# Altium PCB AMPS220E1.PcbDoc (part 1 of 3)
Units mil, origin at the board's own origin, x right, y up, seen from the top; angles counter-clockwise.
Board outline 4800 x 2800 mil, 4 copper layers (Top Layer, GND_Split, GROUND, Bottom Layer), stack 62.6 mil thick; 263 components, 127 nets, 663 pads, 225 vias.
Unrouted connection lines stored in the file: 38.
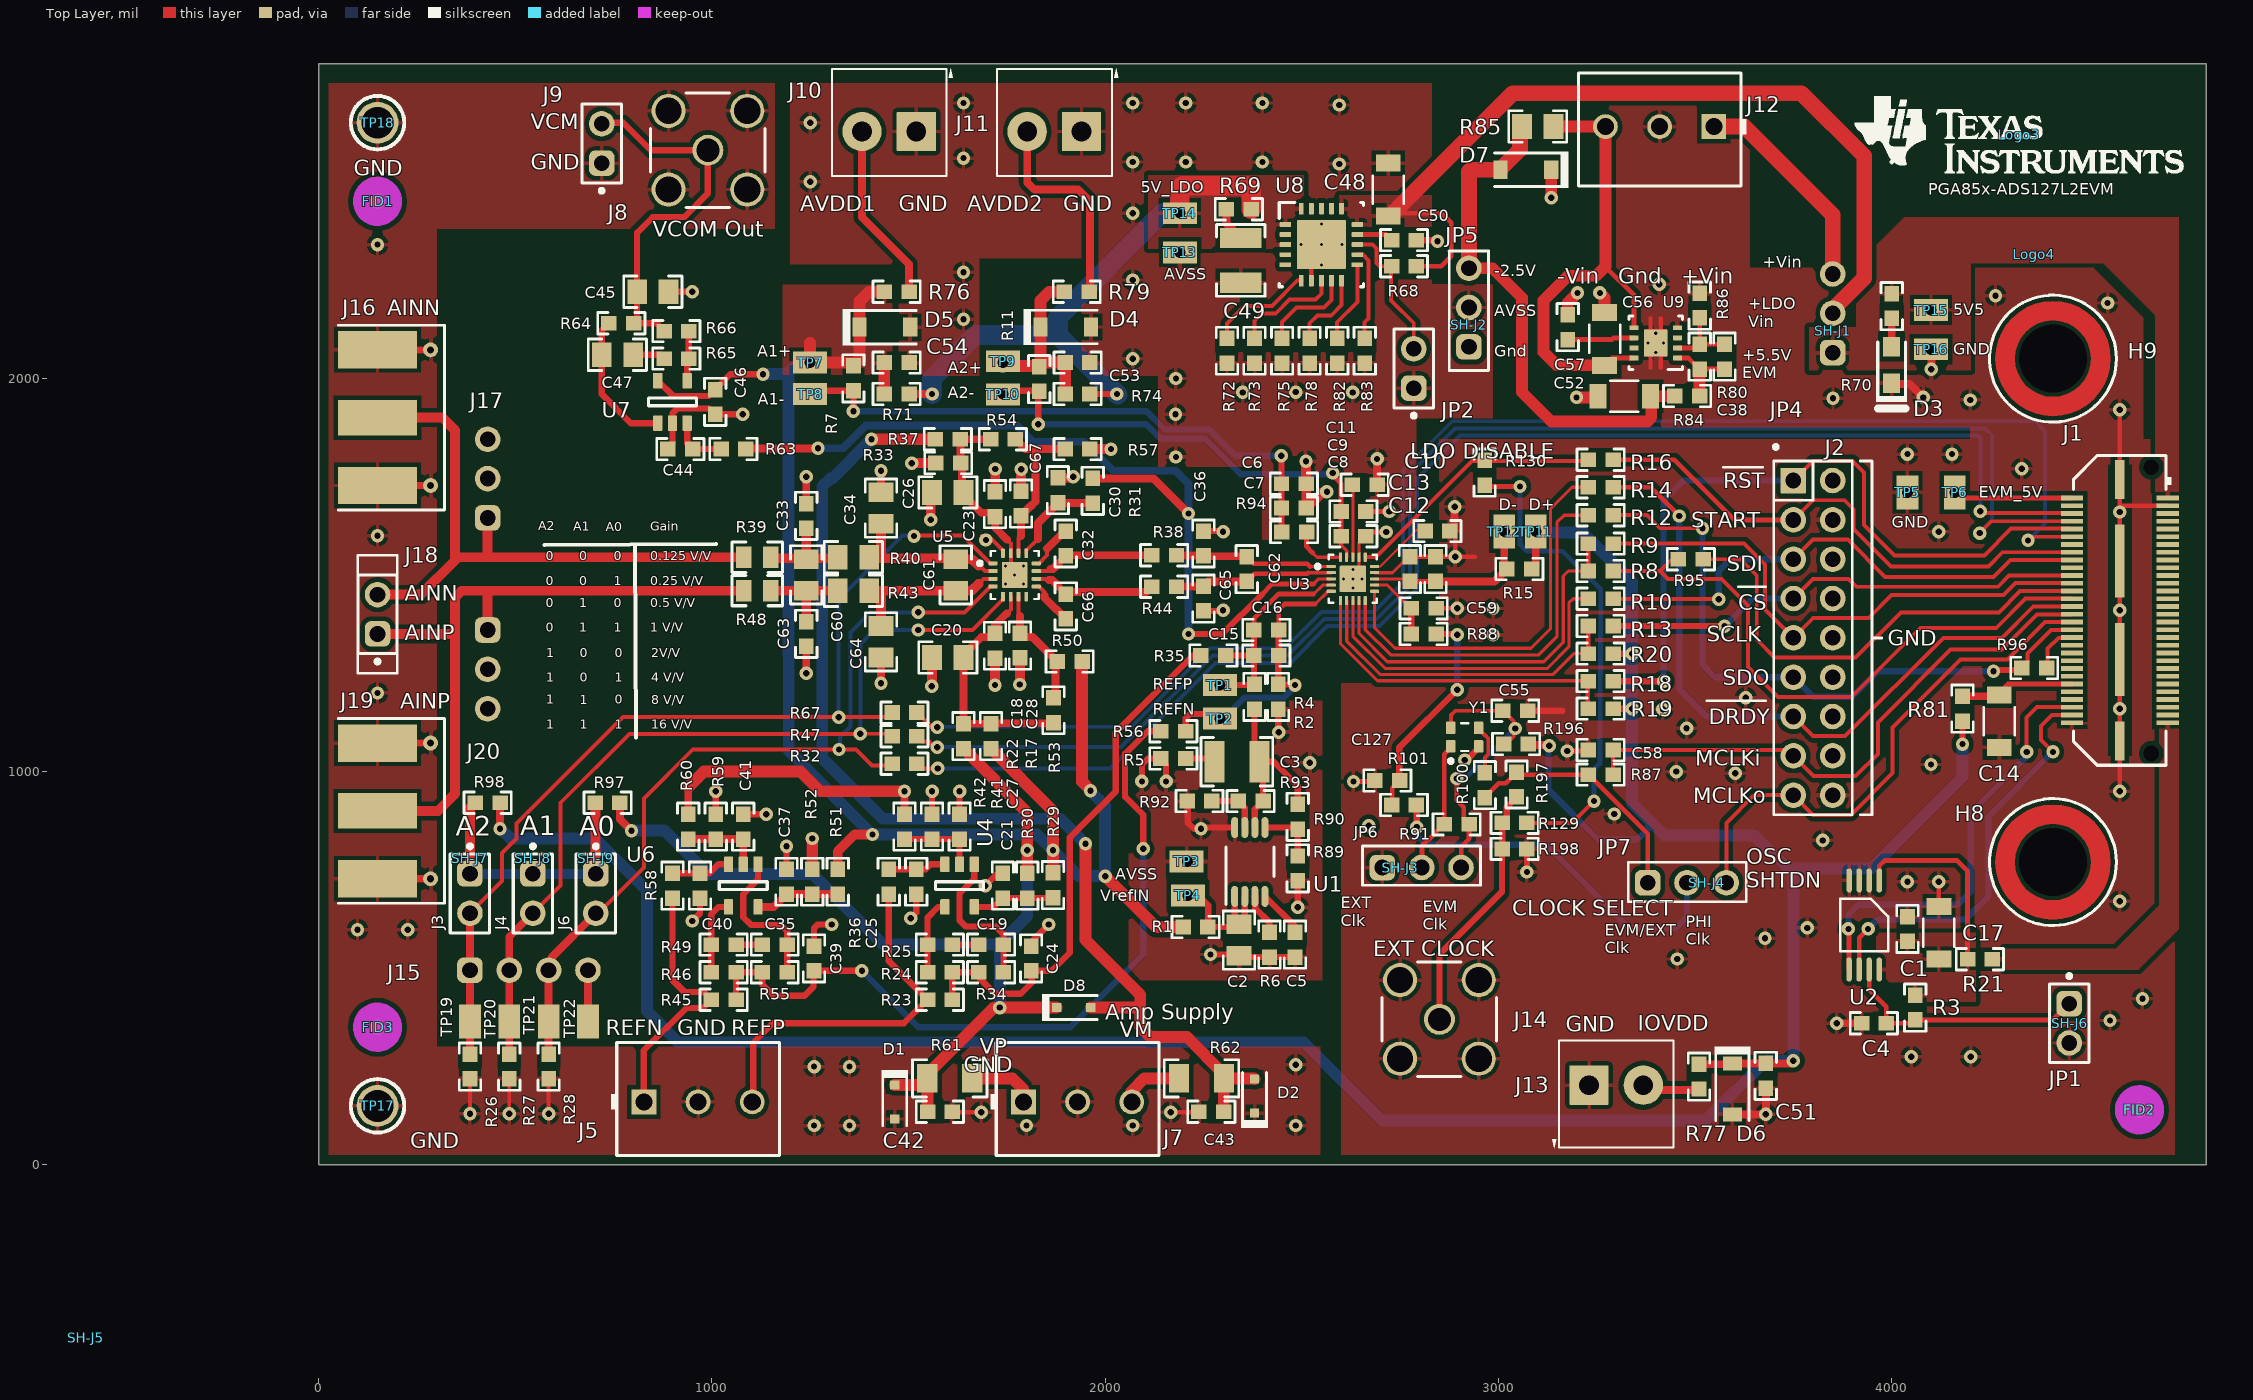
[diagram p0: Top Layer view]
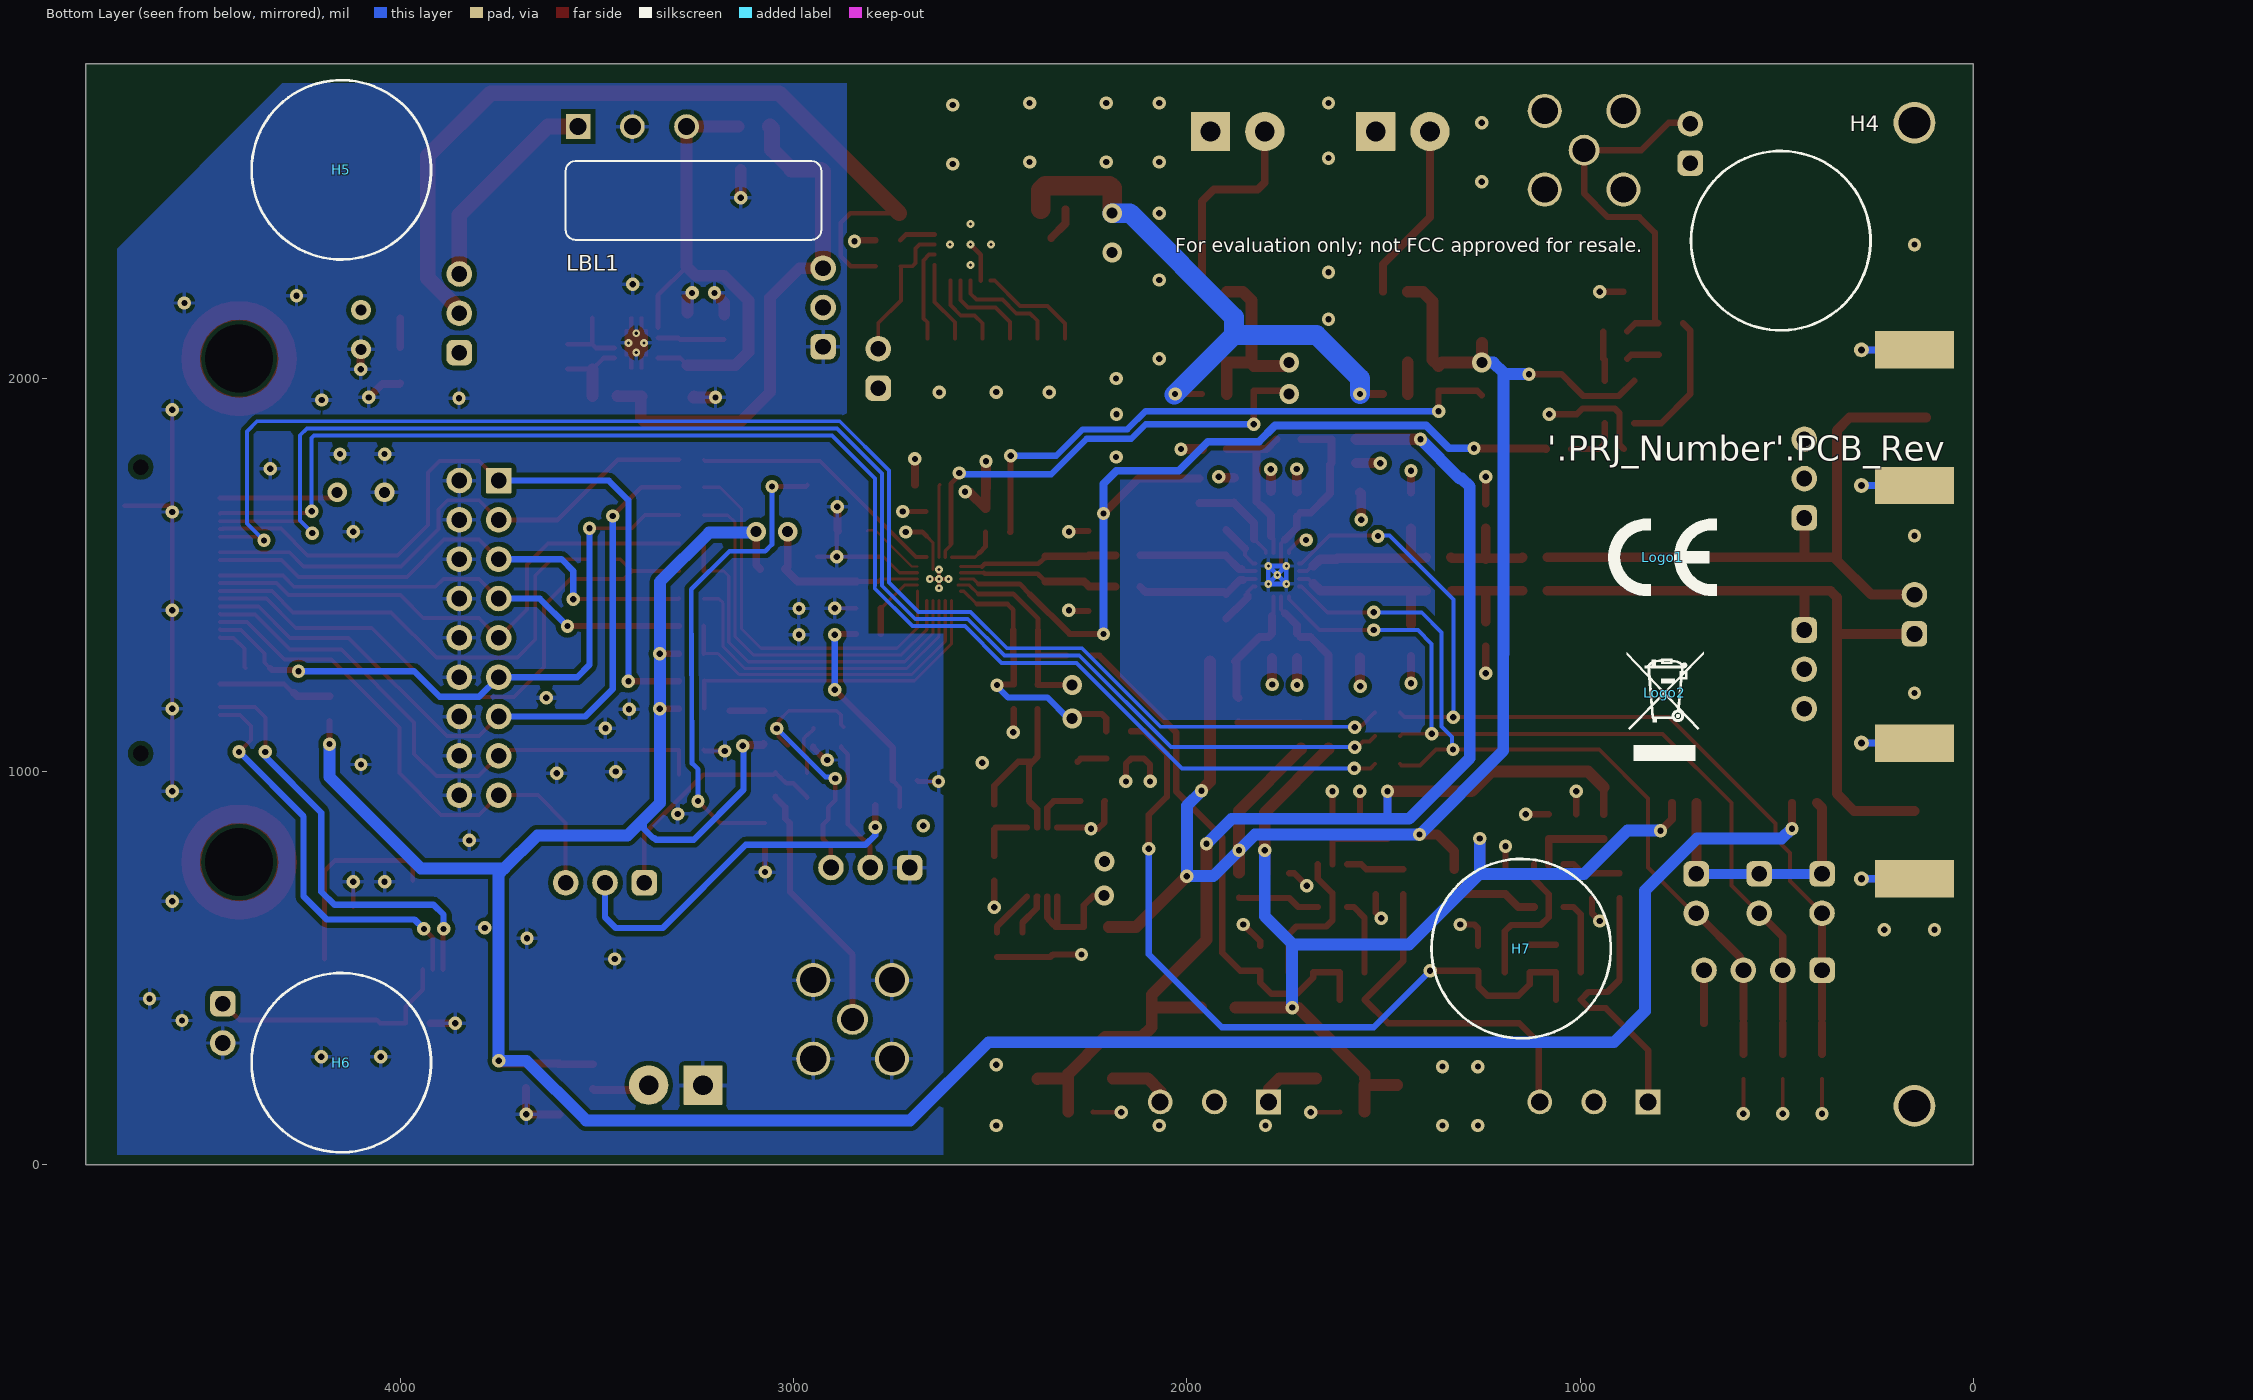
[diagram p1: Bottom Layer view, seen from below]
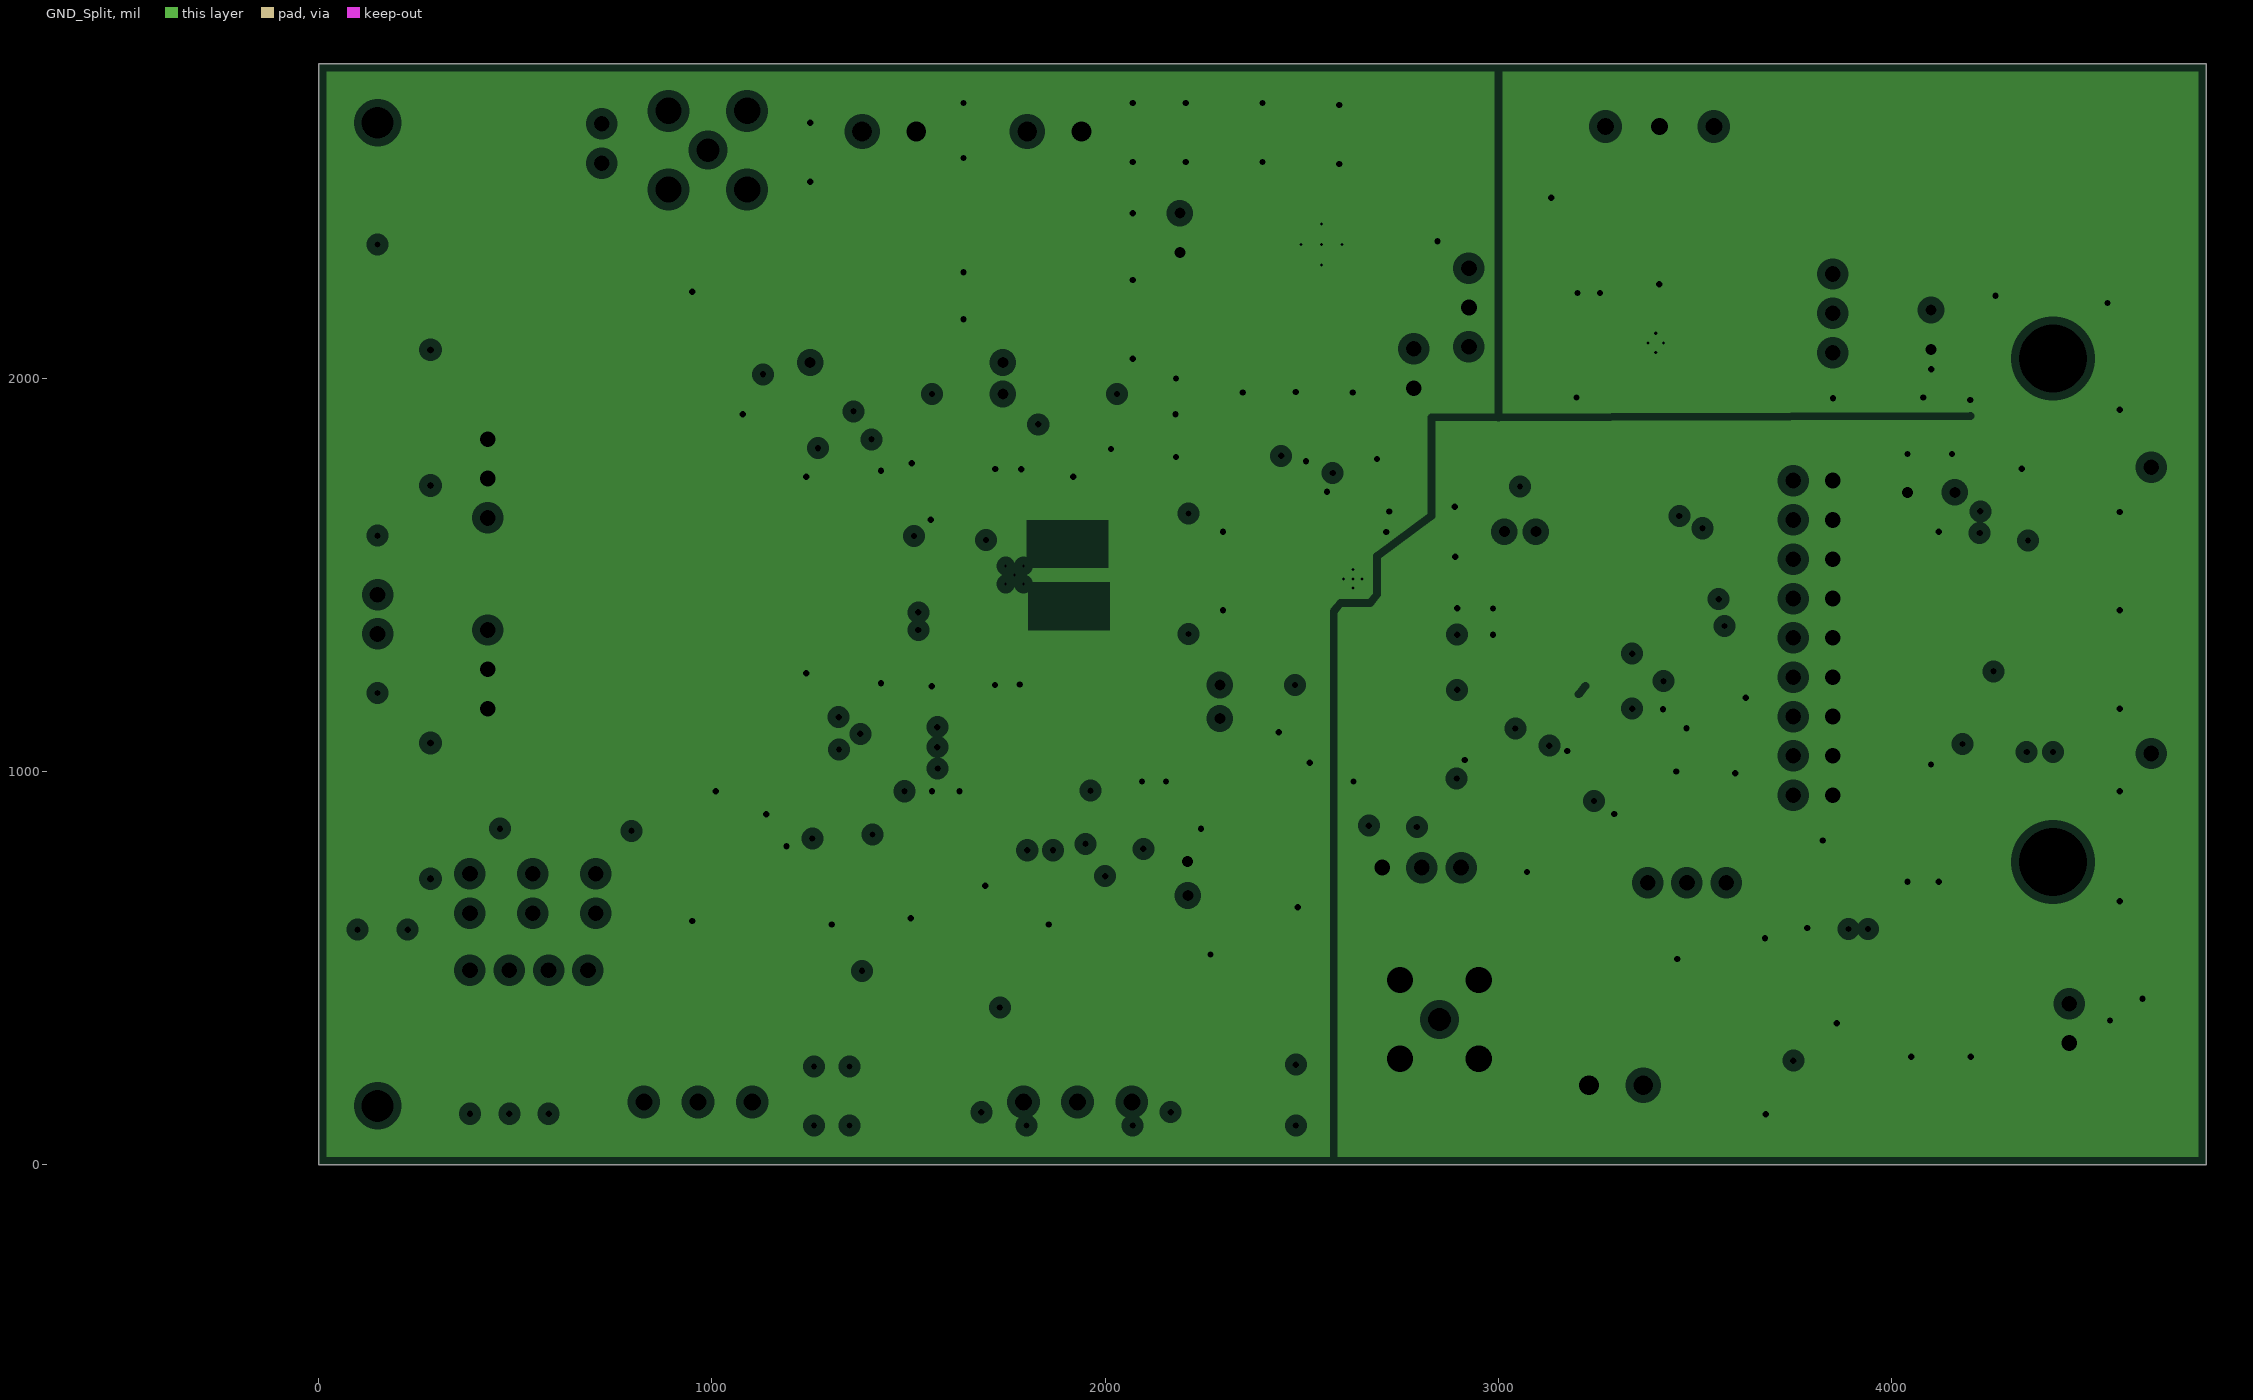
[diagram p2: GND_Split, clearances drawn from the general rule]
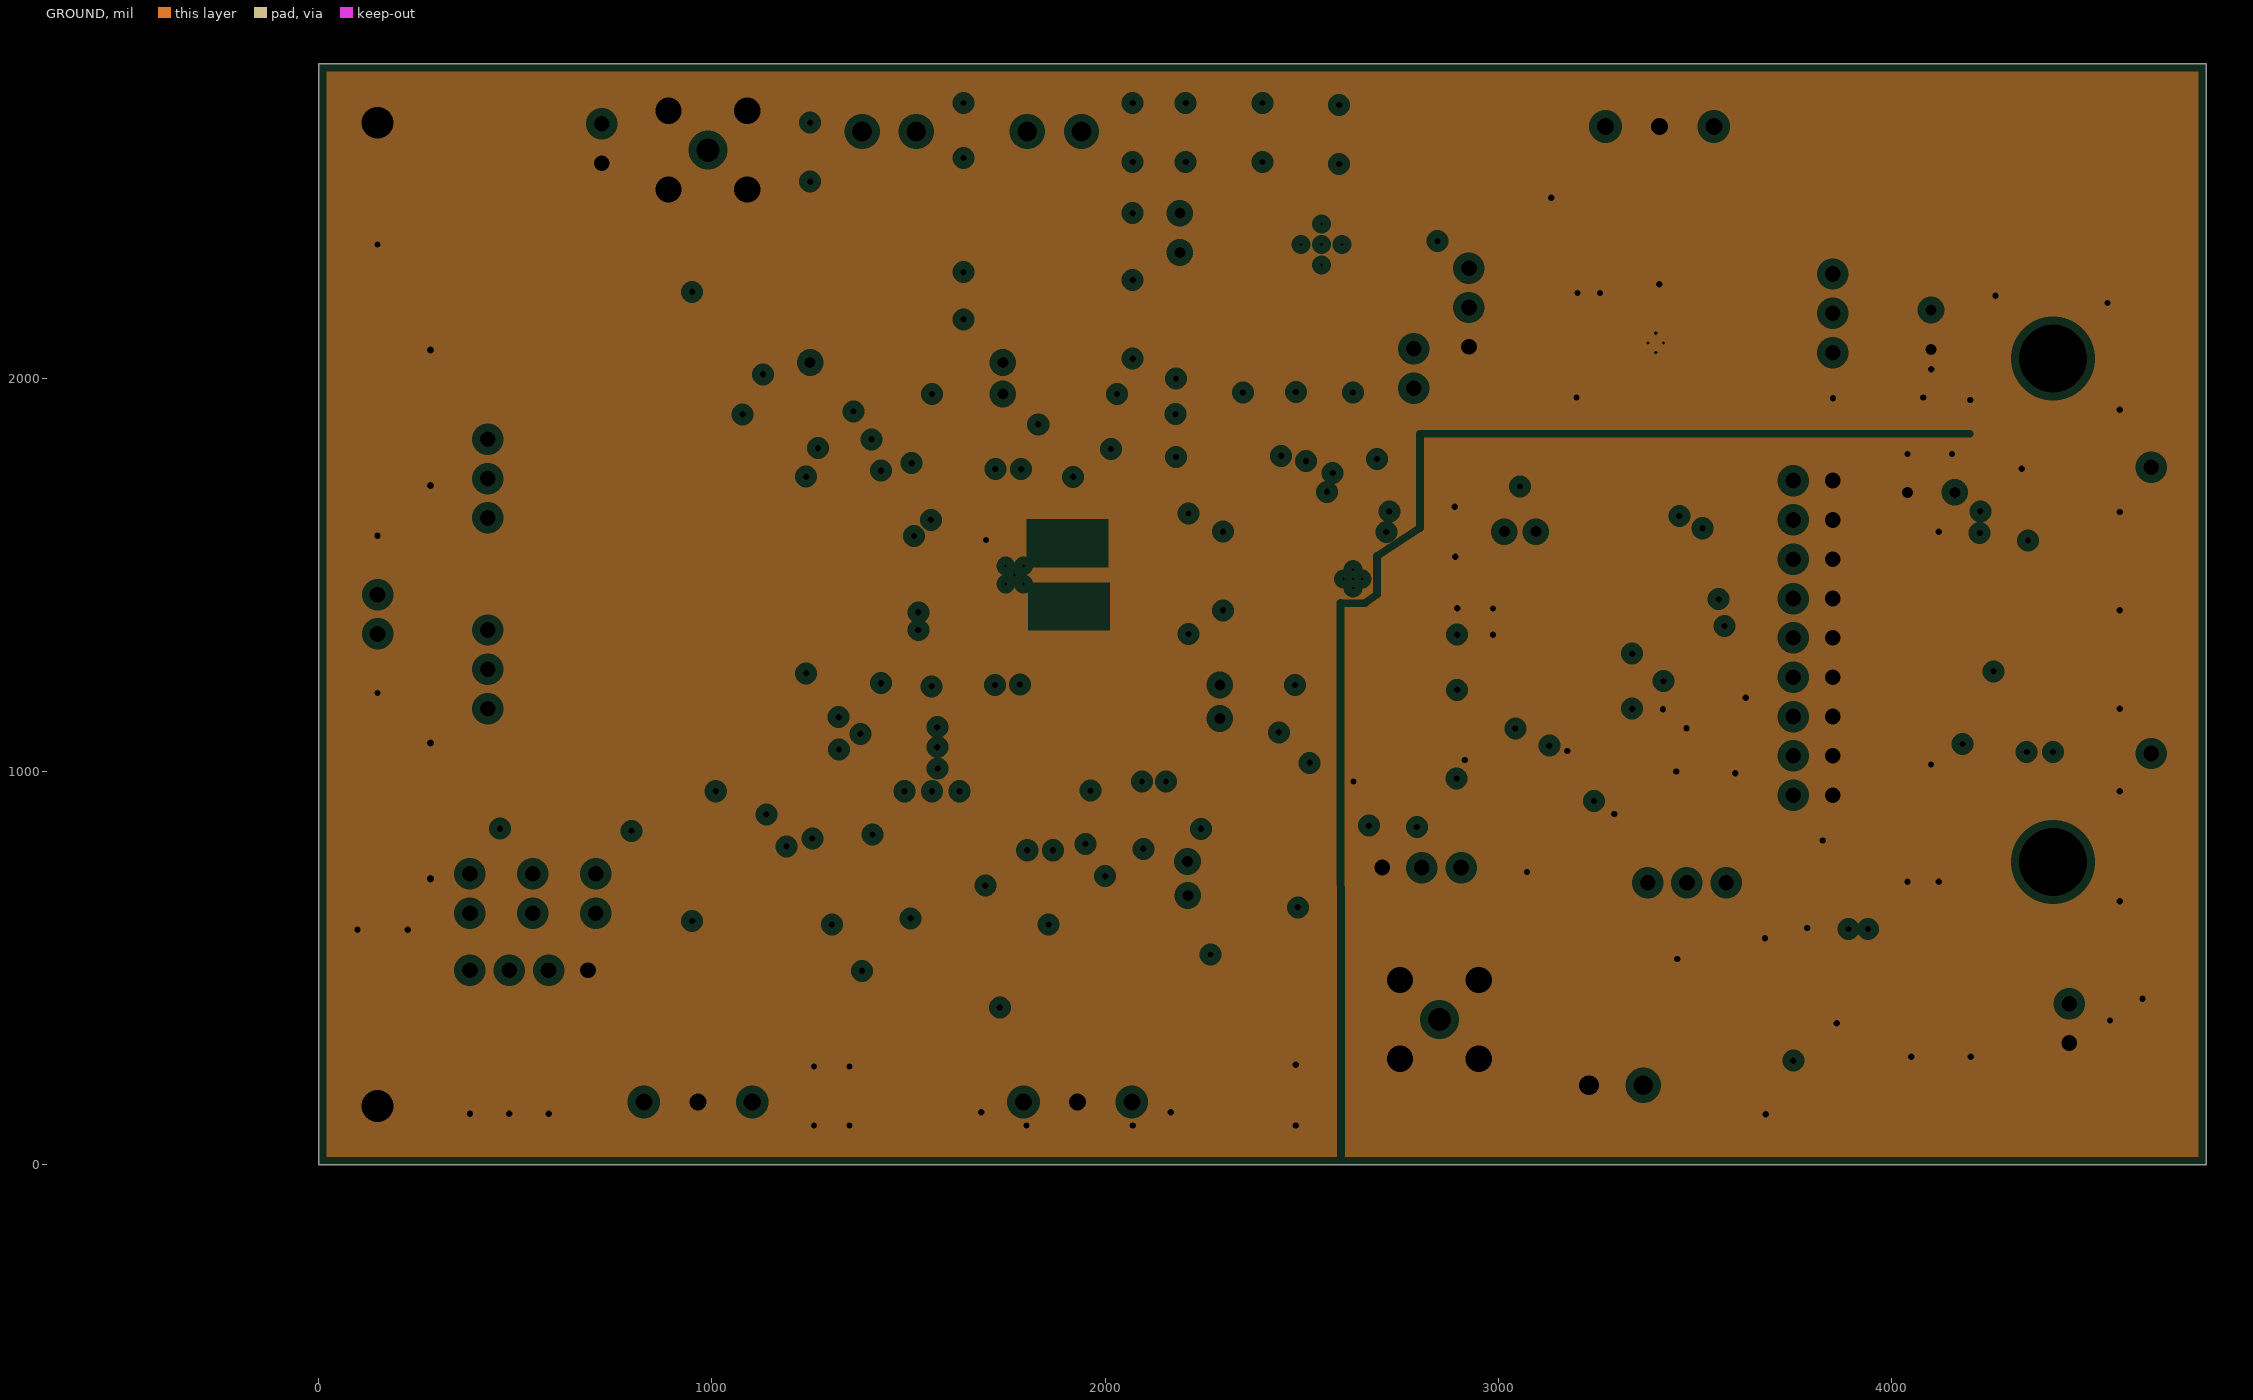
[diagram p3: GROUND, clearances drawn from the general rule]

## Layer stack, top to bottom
Top Solder: solder mask 0.4, Solder Resist, Dk 3.5
Top Layer: signal copper 1.4
Dielectric 2: prepreg 9, FR-4, Dk 4.2
GND_Split: plane copper 1.4, net (Multiple Nets)
Dielectric1: core 39, FR-4, Dk 4.2
GROUND: plane copper 1.4, net GND
Dielectric 3: prepreg 9, FR-4, Dk 4.2
Bottom Layer: signal copper 1.4
Bottom Solder: solder mask 0.4, Solder Resist, Dk 3.5

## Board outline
0,0 0,2800 4800,2800 4800,0

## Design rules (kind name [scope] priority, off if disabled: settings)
AcuteAngle [All] p1: minimum=4.50000000000000E+0001 checktracksonly=FALSE
AssemblyTestPointUsage [All] p1: valid=2
BoardOutlineClearance BoardOutlineClearance_MountingHoles [OnCopper and InComponentClass('Mounting Holes')] p1: gap=39.37 ignorepadtopadclearanceinfootprint=FALSE
BoardOutlineClearance BoardOutlineClearance_Poly [OnCopper and IsPoly] p2: gap=25 ignorepadtopadclearanceinfootprint=FALSE
BoardOutlineClearance BoardOutlineClearance_SMA [InComponent('J3') OR InComponent('J6')] p3: gap=75 ignorepadtopadclearanceinfootprint=FALSE except(15: Track-OutlineEdge; 20: SMDPad-OutlineEdge; 25: Text-OutlineEdge)
BoardOutlineClearance [OnCopper and Not InComponentClass('Logo') and not InComponentClass('FiducialMark') and not InRegion(1000,500,4000,800) and not InPoly] p4: gap=50 ignorepadtopadclearanceinfootprint=FALSE
Clearance Clearance_Keepouts [((IsTrack Or IsArc) And Not InPoly) And IsFree and IsKeepOut vs ((IsTrack Or IsArc) And Not InPoly) And IsFree and IsKeepOut] p1: gap=0 ignorepadtopadclearanceinfootprint=FALSE
Clearance Clearance_Poly [InPolygon] p2: gap=12 ignorepadtopadclearanceinfootprint=FALSE
Clearance Clearance_FiducialMark [IsKeepOut and InComponentClass('FiducialMark') vs IsPad and InComponentClass('FiducialMark')] p3: gap=0 ignorepadtopadclearanceinfootprint=FALSE
Clearance [All] p4 off: gap=7.87 ignorepadtopadclearanceinfootprint=FALSE except(7.5: Arc-Arc Arc-Track Track-Track; 7.7: Arc-SMDPad Track-SMDPad SMDPad-SMDPad)
ComponentClearance ComponentClearance_MountingHoles_FiducialMarks [InComponentClass('Mounting Holes') vs InComponentClass('FiducialMark')] p1: gap=50 collisioncheckmode=3 verticalgap=10 showdistances=FALSE
ComponentClearance ComponentClearance_Shunt [InComponentClass('Header') vs InComponentClass('Shunt')] p2: gap=0 collisioncheckmode=3 verticalgap=0 showdistances=FALSE
ComponentClearance ComponentClearance_Logo [InComponentClass('Logo')] p3: gap=50 collisioncheckmode=3 verticalgap=10 showdistances=FALSE
ComponentClearance ComponentClearance_ScrewToNut [(HasFootprint('NY PMS 440 0025 PH')) vs (HasFootprint('Keystone_1902C'))] p4: gap=5 collisioncheckmode=3 verticalgap=10 showdistances=FALSE
ComponentClearance ComponentClearance_MountingHoles [InComponentClass('Mounting Holes')] p5: gap=250 collisioncheckmode=3 verticalgap=100000 showdistances=FALSE
ComponentClearance ComponentClearance_SmallPassives [HasFootprint('0201*') or HasFootprint('0402*') or HasFootprint('0508') or HasFootprint('0603*') or HasFootprint('0612') or HasFootprint('0805*') or HasFootprint('0815*') or HasFootprint('0830*') or HasFootprint('1206*') or HasFootprint('1210*') or HasFootprint('1808*') or HasFootprint('1812*') or HasFootprint('1825*') or HasFootprint('2010*') or HasFootprint('2220*') or HasFootprint('2225*') or HasFootprint('2512*') or HasFootprint('2728*') or HasFootprint('3518*') vs HasFootprint('0201*') or HasFootprint('0402*') or HasFootprint('0508') or HasFootprint('0603*') or HasFootprint('0612') or HasFootprint('0805*') or HasFootprint('0815*') or HasFootprint('0830*') or HasFootprint('1206*') or HasFootprint('1210*') or HasFootprint('1808*') or HasFootprint('1812*') or HasFootprint('1825*') or HasFootprint('2010*') or HasFootprint('2220*') or HasFootprint('2225*') or HasFootprint('2512*') or HasFootprint('2728*') or HasFootprint('3518*')] p6: gap=20 collisioncheckmode=3 verticalgap=10 showdistances=FALSE
ComponentClearance ComponentClearance_THtoSMT [IsThruComponent vs IsSMTComponent] p7: gap=40 collisioncheckmode=3 verticalgap=30 showdistances=FALSE
ComponentClearance ComponentClearance_THtoTH [IsThruComponent vs IsThruComponent] p8: gap=30 collisioncheckmode=3 verticalgap=30 showdistances=FALSE
ComponentClearance [All] p9: gap=30 collisioncheckmode=3 verticalgap=10 showdistances=FALSE
DiffPairsRouting [All] p1: maxlimit=100 minlimit=10 mostfreqgap=10 toplayer_minwidth=15 toplayer_maxwidth=15 toplayer_prefwidth=15 bottomlayer_minwidth=15 bottomlayer_maxwidth=15 bottomlayer_prefwidth=15 maxuncoupledlength=1000
FabricationTestPointUsage TestPointUsage [All] p1: valid=2 allowmultiple=FALSE
FabricationTestpoint Testpoint [All] p1: side=3 testpointundercomponent=TRUE minsize=40 maxsize=100 preferedsize=60 minholesize=0 maxholesize=40 preferedholesize=32 testpointgrid=1 allowsidetop=TRUE allowsidebottom=TRUE usegrid=TRUE gridtolerance=0.01
FanoutControl Fanout_LCC [IsLCC] p1: bgadir=Out bgaviamode=Centered fanoutstyle=Auto fanoutdirection=Alternating viagrid=1 // Fanout_LCC (Default Rule)
FanoutControl Fanout_BGA [IsBGA] p2: bgadir=Out bgaviamode=Centered fanoutstyle=Auto fanoutdirection=Alternating viagrid=1 // Fanout_BGA (Default Rule)
FanoutControl Fanout_Default [All] p4: bgadir=Out bgaviamode=Centered fanoutstyle=Auto fanoutdirection=Alternating viagrid=1 // Fanout_Default (Default Rule)
FanoutControl Fanout_Small [(CompPinCount < 5)] p5: bgadir=Out bgaviamode=Centered fanoutstyle=Auto fanoutdirection=OutThenIn viagrid=1 // Fanout_Small (Default Rule)
HoleSize [All] p1: absolutevalues=TRUE maxlimit=251 minlimit=7.87 maxpercent=80.000 minpercent=20.000
MinimumAnnularRing MinimumAnnularRing_ThermalPadVias [IsVia and InAnyComponent] p1: minimumring=5.91
MinimumAnnularRing [All] p2: minimumring=7.87
MinimumSolderMaskSliver MinimumSolderMaskSliver_Logo [InComponentClass('Logo') vs InComponentClass('Logo')] p1: minsoldermaskwidth=0.7
MinimumSolderMaskSliver MinimumSolderMaskSliver_PHI [InComponent('J1')] p2: minsoldermaskwidth=3.7
MinimumSolderMaskSliver [All] p3: minsoldermaskwidth=3.94
PlaneClearance [All] p1: clearance=20
PlaneConnect [All] p1: pad.planeconnectstyle=Relief pad.reliefexpansion=10 pad.reliefentries=4 pad.reliefconductorwidth=10 pad.reliefairgap=10 via.planeconnectstyle=Direct via.reliefexpansion=10 via.reliefentries=4 via.reliefconductorwidth=9 via.reliefairgap=8
PolygonConnect [All] p1: connectstyle=Relief reliefconductorwidth=10 reliefentries=4 polygonreliefangle="90 Angle" airgapwidth=10
RoutingVias ThermalPadVias [IsVia and InAnyComponent] p1: holewidth=7.87 width=19.68 viastyle="Through Hole" minholewidth=7.87 minwidth=19.68 maxholewidth=12.99 maxwidth=23.62
RoutingVias [All] p2: holewidth=16 width=34 viastyle="Through Hole" minholewidth=7.87 minwidth=26 maxholewidth=40 maxwidth=65
SilkToBoardRegionClearance [Not ((IsComment or IsDesignator) And (Hide <> 'False')) and not InRegion(1000,500,4000,800)] p1:
SilkToSilkClearance SilkToSilkClearance_Pb-FreeLogo [(HasFootprint('Pb-Free_Overlay_Medium') OR HasFootprint('Pb-Free_Overlay_Small')) vs (HasFootprint('Pb-Free_Overlay_Medium') OR HasFootprint('Pb-Free_Overlay_Small'))] p1: silktosilkclearance=0
SilkToSilkClearance [All] p2: silktosilkclearance=3.94
SilkToSolderMaskClearance SilkToComponentPadClearance [(IsPad or IsFill or IsRegion) and InAnycomponent] p1: minsilkscreentomaskgap=5 clearancetoexposedcopper=TRUE
SilkToSolderMaskClearance "Silk to Solder Mask Opening" [All] p2: minsilkscreentomaskgap=3.94 clearancetoexposedcopper=FALSE
SolderMaskExpansion [All] p1: expansion=1.97 istentingtop=FALSE
UnRoutedNet [All] p1: checkbadconnections=TRUE
Width [All] p1: maxlimit=100 minlimit=6 preferedwidth=10 checkconnectedcopper=TRUE
13 further rules are at their usual default settings.

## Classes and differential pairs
component class Shunt: SH-J1 SH-J2 SH-J3 SH-J4 SH-J5 SH-J6 SH-J7 SH-J8 SH-J9
component class Logo: Logo3
component class Label: LBL1
component class Header: J2 J3 J4 J6 J9 J15 J17 J18 J20 JP1 JP2 JP4 JP5 JP6 JP7
component class FiducialMark: FID1 FID2 FID3
component class AssemblyNote: ZZ1 ZZ2 ZZ3 ZZ4
component class AMPS220E1_Power_Clock: C38 C48 C49 C50 C51 C52 C53 C54 C55 C56 C57 C58 C59 C127 D3 D4 D5 D6 D7 J10 J11 J12 J13 J14 JP2 JP4 JP5 JP6 JP7 R68 R69 R70 R71 R72 R73 R74 R75 R76 R77 R78 R79 R80 R81 R82 R83 R84 R85 R86 R87 R88 R91 R100 R101 R129 R196 R197 R198 TP13 TP14 TP15 TP16 TP17 TP18 U8 U9 Y1
component class AMPS220E1_2: C18 C19 C20 C21 C23 C24 C25 C26 C27 C28 C30 C32 C33 C34 C35 C36 C37 C39 C40 C41 C42 C43 C44 C45 C46 C47 C60 C61 C62 C63 C64 C65 C66 C67 D1 D2 D8 J3 J4 J5 J6 J7 J8 J9 J15 J16 J17 J18 J19 J20 R17 R22 R23 R24 R25 R26 R27 R28 R29 R30 R31 R33 R34 R35 R36 R37 R38 R39 R40 R41 R42 R43 R44 R45 R46 R48 R49 R50 R51 R52 R53 R54 R55 R56 R57 R58 R59 R60 R61 R62 R63 R64 R65 R66 R97 R98 TP19 TP20 TP21 TP22 U4 U5 U6 U7
component class AMPS220E1: C1 C2 C3 C4 C5 C6 C7 C8 C9 C10 C11 C12 C13 C14 C15 C16 C17 J1 J2 JP1 R1 R2 R3 R4 R5 R6 R7 R8 R9 R10 R11 R12 R13 R14 R15 R16 R18 R19 R20 R21 R32 R47 R67 R89 R90 R92 R93 R94 R95 R96 R130 TP1 TP2 TP3 TP4 TP5 TP6 TP7 TP8 TP9 TP10 TP11 TP12 U1 U2 U3
component class AMPS220E1_Hardware: FID1 FID2 FID3 H4 H5 H6 H7 H8 H9 LBL1 Logo1 Logo2 Logo3 Logo4 SH-J1 SH-J2 SH-J3 SH-J4 SH-J5 SH-J6 SH-J7 SH-J8 SH-J9 ZZ1 ZZ2 ZZ3 ZZ4

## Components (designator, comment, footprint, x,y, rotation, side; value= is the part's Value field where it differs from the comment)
C1 "C0603C104J3RACTU" 0603 4040,600 r270 top value=0.1uF
C2 "GRM21BR71A106KA73L" 0805_HV 2340.53,571.74 r270 top value=10uF
C3 "CL32B226KAJNFNE" 1210_270 2335,1025 r180 top value=22uF
C4 "C0603C104J3RACTU" 0603 3954.77,360 r180 top value=0.1uF
C5 "CGA3E1X7R1C105K080AC" 0603 2482.95,560 r270 top value=1uF
C6 "C0603C105K3RACTU" 0603 2480,1732 r180 top value=1uF
C7 "C0603C104J3RACTU" 0603 2480,1670 r0 top value=0.1uF
C8 "C0603C105K3RACTU" 0603 2631.38,1598.5 r180 top value=1uF
C9 "C0603C104J3RACTU" 0603 2631.38,1661.5 r0 top value=0.1uF
C10 "C0603C105K3RACTU" 0603 2845,1611.5 r180 top value=1uF
C11 "C0603C105K3RACTU" 0603 2660,1729.26 r180 top value=1uF
C12 "C0603C105K3RACTU" 0603 2840,1515 r270 top value=1uF
C13 "C0603C104J3RACTU" 0603 2775,1515 r90 top value=0.1uF
C14 "C1206C106K3RACTU" 1206_190 4273.43,1128.39 r270 top value=10uF
C15 "C0603C105K3RACTU" 0603 2410,1295 r180 top value=1uF
C16 "C0603C104J3RACTU" 0603 2410,1360 r0 top value=0.1uF
C17 "C1206C106K3RACTU" 1206_190 4120,590 r270 top value=10uF
C18 "C0603C104J3RACTU" 0603 1720,1320 r270 top value=0.1uF
C19 "C0603C104J3RACTU" 0603 1710,560 r180 top value=0.1uF
C20 "GRM21BR71A106KA73L" 0805_HV 1600,1290 r180 top value=10uF
C21 "C0603C104J3RACTU" 0603 1740,710 r270 top value=0.1uF
C23 "C0603C104J3RACTU" 0603 1720,1680 r90 top value=0.1uF
C24 "C0603C104J3RACTU" 0603 1812,525 r90 top value=0.1uF
C25 "GRM1885C1E102JA01D" 0603 1520,720 r90 top value=1000pF
C26 "GRM21BR71A106KA73L" 0805_HV 1600,1710 r180 top value=10uF
C27 "C0603C104J3RACTU" 0603 1630,860 r270 top value=0.1uF
C28 "885012206095" 0603 1783.46,1320.47 r270 top value=0.1uF
C30 "C0603C102J5GAC" 0603 1880,1715.5 r90 top value=1000pF
C32 "06031A250GAT2A" 0603 1900,1580 r90 top value=25pF
C33 "06035A101FAT2A" 0603 1240,1650 r90 top value=100pF
C34 "GRM2195C2A100JZ01D" 0805_HV 1430,1670 r90 top value=10pF
C35 "C0603C104J3RACTU" 0603 1160,560 r180 top value=0.1uF
C36 "C0603C510F5GAC7867" 0603 2250,1580 r90 top value=51pF
C37 "C0603C104J3RACTU" 0603 1190,720 r270 top value=0.1uF
C38 "C0603C103F3GACTU" 0603 3575,2055 r90 top value=0.01uF
C39 "C0603C104J3RACTU" 0603 1260,525 r90 top value=0.1uF
C40 "GRM1885C1E102JA01D" 0603 970,710 r90 top value=1000pF
C41 "C0603C104J3RACTU" 0603 1080,860 r270 top value=0.1uF
C42 "C0603C105K3RACTU" 0603 1580,135 r180 top value=1uF
C43 "C0603C105K3RACTU" 0603 2270,135 r0 top value=1uF
C44 "CGA3E1X7R1C105K080AC" 0603 920,1820 r180 top value=1uF
C45 "GRM21BR71A106KA73L" 0805_HV 850,2220 r0 top value=10uF
C46 "C0603C104J3RACTU" 0603 1008.84,1940 r90 top value=0.1uF
C47 "CGA4J2C0G1H333J125AA" 0805_HV 760,2060 r180 top value=0.033uF
C48 "C1206C106K3RACTU" 1206_190 2720,2480 r270 top value=10uF
C49 "CL32B226KAJNFNE" 1210_270 2345,2300 r270 top value=22uF
C50 "C0603C105K3RACTU" 0603 2760,2351.38 r180 top value=1uF
C51 "C0603C105K3RACTU" 0603 3680,226.53 r90 top value=1uF
C52 "C1206C106K3RACTU" 1206_190 3319.98,1954.42 r0 top value=10uF
C53 "C0603C105K3RACTU" 0603 1930,2040 r180 top value=1uF
C54 "C0603C105K3RACTU" 0603 1470,2040 r180 top value=1uF
C55 "C0603C104J3RACTU" 0603 3042.91,1154.7 r0 top value=0.1uF
C56 "C1206C106K3RACTU" 1206_190 3270,2100 r270 top value=10uF
C57 "C0603C103F3GACTU" 0603 3176.57,2130 r90 top value=0.01uF
C58 "GRM1885C1H100JA01D" 0603 3260,1055 r0 top value=10pF
C59 "GRM1885C1H100JA01D" 0603 2809.88,1415 r180 top value=10pF
C60 "08055A101JAT2A" 0805_HV 1240,1500 r270 top value=100pF
C61 "08051A101JAT2A" 0805_HV 1620,1500 r270 top value=100pF
C62 "C0603C561J5GACTU" 0603 2360,1515 r270 top value=560pF
C63 "06035A101FAT2A" 0603 1240,1350 r90 top value=100pF
C64 "GRM2195C2A100JZ01D" 0805_HV 1430,1330 r90 top value=10pF
C65 "C0603C510F5GAC7867" 0603 2250,1440 r90 top value=51pF
C66 "06031A250GAT2A" 0603 1900,1420 r270 top value=25pF
C67 "885012206095" 0603 1786.14,1681.5 r270 top value=0.1uF
C127 "GRM1885C1H100JA01D" 0603 2717.65,977.39 r0 top value=10pF
D1 "CDSOD323-T36S" SOD-323 1465,160 r270 top value=36V
D2 "CDSOD323-T36S" SOD-323 2380,175 r90 top value=36V
D3 "APT2012LZGCK" APT2012_Green 4000,2033.66 r270 top value=Green
D4 "MMSZ4690T1G" SOD-123 1900,2130.51 r0 top value=5.6V
D5 "MMSZ4690T1G" SOD-123 1440,2130 r0 top value=5.6V
D6 "MMSZ4690T1G" SOD-123 3595,192.97 r270 top value=5.6V
D7 "MMSZ4683T1G" SOD-123 3070,2530.32 r180 top value=3V
D8 "CDSOD323-T36S" SOD-323 1920,400 r0 top value=36V
FID1 "Fiducial" Fiducial10-30 150,2450 r0 top
FID2 "Fiducial" Fiducial10-30 4630,140 r0 top
FID3 "Fiducial" Fiducial10-30 150,350 r0 top
H4 "SJ-5303 (CLEAR)" Bumpon_SJ5003Transparent 490,2350 r180 bottom
H5 "SJ-5303 (CLEAR)" Bumpon_SJ5003Transparent 4150,2530 r180 bottom
H6 "SJ-5303 (CLEAR)" Bumpon_SJ5003Transparent 4150,260 r180 bottom
H7 "SJ-5303 (CLEAR)" Bumpon_SJ5003Transparent 1150,550 r180 bottom
H8 "9774050360R" Wurth_WA-SMSI 4410,770 r0 top
H9 "9774050360R" Wurth_WA-SMSI 4410,2050 r0 top locked
J1 "QTH-030-01-L-D-A" Samtec_QTH-030-01-x-D-A 4580,1410 r270 top
J2 "TSW-109-07-G-D" Samtec_TSW-109-07-G-D 3800,1340 r270 top
J3 "A2" TSW-102-07-G-S 385,690 r270 top
J4 "A1" TSW-102-07-G-S 545,690 r270 top
J5 "0393570003" MOLEX_39357-0003 965,160 r0 top
J6 "A0" TSW-102-07-G-S 705,690 r270 top
J7 "0393570003" MOLEX_39357-0003 1930,160 r0 top
J8 "901-144-8RFX" AMPHENOL_901-144-8RFX 990,2580 r0 top
J9 "TSW-102-07-G-S" TSW-102-07-G-S 720,2596.98 r90 top
J10 "ED555/2DS" TERM_BLK_ED555-2DS 1520,2627.48 r180 top
J11 "ED555/2DS" TERM_BLK_ED555-2DS 1940,2627.48 r180 top
J12 "0393570003" MOLEX_39357-0003 3410,2640 r180 top
J13 "ED555/2DS" TERM_BLK_ED555-2DS 3230.5,202.82 r0 top
J14 "901-144-8RFX" AMPHENOL_901-144-8RFX 2850,370 r0 top
J15 "TSW-104-07-G-S" TSW-104-07-G-S 535,495 r0 top
J16 "142-0701-801" Johnson_142-0701-801 150,1900 r90 top
J17 "TSW-103-07-G-S" TSW-103-07-G-S 430,1745 r90 top
J18 "Input_short" TSW-102-07-G-S 150,1400 r90 top
J19 "142-0701-801" Johnson_142-0701-801 150,900 r90 top
J20 "TSW-103-07-G-S" TSW-103-07-G-S 430,1260 r270 top
JP1 "EEPROM_EN" TSW-102-07-G-S 4451.29,360 r270 top
JP2 "/LDO_EN" TSW-102-07-G-S 2784.71,2025 r90 top
JP4 "TSW-103-07-G-S" TSW-103-07-G-S 3850,2165.19 r90 top
JP5 "TSW-103-07-G-S" TSW-103-07-G-S 2925,2180 r90 top
JP6 "TSW-103-07-G-S" TSW-103-07-G-S 2805,756 r0 top
JP7 "TSW-103-07-G-S" TSW-103-07-G-S 3479.49,717.4 r0 top
LBL1 "THT-14-423-10" Label_650x200 3254.53,2452.19 r180 bottom
Logo1 "CE Mark" CE_Mark_5mm 790.52,1545 r180 bottom
Logo2 "WEEE logo" WEEE_Minimum 785.59,1200 r180 bottom
Logo3 "Texas Instruments" TI_Stacked_Overlay_Small 4324.11,2619.41 r0 top
Logo4 "FCC disclaimer" FCC_disclaimer 4362.44,2315.19 r0 top
R1 "RC0603JR-070RL" 0603 2230,605 r0 top value=0
R2 "RC0603JR-070RL" 0603 2380,1190 r90 top value=0
R3 "RC0603FR-0710KL" 0603 4060,400 r270 top value=10.0k
R4 "RC0603JR-070RL" 0603 2440,1190 r90 top value=0
R5 "ERJ-L03KF47MV" 0603 2173.54,1033.06 r0 top value=0.047
R6 "RG1608P-124-B-T5" 0603 2417.95,560 r90 top value=120k
R7 "ERJ-L03KF10CV" 0603 1360,2000 r90 top value=0.1
R8 "CRCW060310R0FKEAHP" 0603 3260,1510 r0 top value=10.0
R9 "CRCW060310R0FKEAHP" 0603 3260,1579.57 r0 top value=10.0
R10 "CRCW060310R0FKEAHP" 0603 3260,1439.6 r0 top value=10.0
R11 "ERJ-L03KF10CV" 0603 1832.39,1998 r90 top value=0.1
R12 "CRCW060310R0FKEAHP" 0603 3260,1651.9 r0 top value=10.0
R13 "CRCW060310R0FKEAHP" 0603 3260,1370 r0 top value=10.0
R14 "CRCW060310R0FKEAHP" 0603 3260,1723.04 r0 top value=10.0
R15 "ERJ-L03KF10CV" 0603 3053.31,1515 r0 top value=0.1
R16 "CRCW060310R0FKEAHP" 0603 3260,1792.95 r0 top value=10.0
R17 "RC0603JR-070RL" 0603 1710,1090 r270 top value=0
R18 "CRCW060310R0FKEAHP" 0603 3260,1230 r0 top value=10.0
R19 "CRCW0603100KFKEA" 0603 3260,1160 r0 top value=100k
R20 "CRCW0603100KFKEA" 0603 3260,1300 r0 top value=100k
R21 "RC0603JR-070RL" 0603 4224.3,523.07 r180 top value=0
R22 "RC0603JR-070RL" 0603 1640,1090 r270 top value=0
R23 "RC0603JR-070RL" 0603 1580,420 r180 top value=0
R24 "CRCW06031K00FKEA" 0603 1580,490 r180 top value=1.00k
R25 "CRCW0603100RFKEA" 0603 1580,560 r0 top value=100
R26 "RCG060310K0FKEA" 0603 385,250 r90 top value=10.0k
R27 "RCG060310K0FKEA" 0603 485,250 r90 top value=10.0k
R28 "RCG060310K0FKEA" 0603 585,250 r90 top value=10.0k
R29 "RC0603JR-070RL" 0603 1867.43,711.15 r270 top value=0
R30 "RC0603JR-070RL" 0603 1802,710 r90 top value=0
R31 "CRCW06031K00FKEA" 0603 1968.35,1713.84 r270 top value=1.00k
R32 "CRCW060310R0FKEAHP" 0603 1490,1020 r0 top value=10.0
R33 "RC0603JR-070RL" 0603 1601.13,1784.71 r180 top value=0
R34 "CRCW0603100RFKEA" 0603 1710,490 r180 top value=100
R35 "RC0603JR-070RL" 0603 2275.08,1295 r0 top value=0
R36 "CRCW06031K00FKEA" 0603 1450,720 r270 top value=1.00k
R37 "RC0603JR-070RL" 0603 1600.16,1845 r180 top value=0
R38 "RT0603BRD0747R5L" 0603 2150,1550 r0 top value=47.5
R39 "5106" 5106 1115,1545 r0 top value=0
R40 "RG2012P-101-B-T5" 0805_HV 1360,1545 r0 top value=100
R41 "RC0603JR-070RL" 0603 1560,860 r270 top value=0
R42 "RC0603JR-070RL" 0603 1490,860 r90 top value=0
R43 "RG2012P-101-B-T5" 0805_HV 1360,1460 r0 top value=100
R44 "RT0603BRD0747R5L" 0603 2150,1470 r0 top value=47.5
R45 "RC0603JR-070RL" 0603 1030,420 r180 top value=0
R46 "CRCW06031K00FKEA" 0603 1030,490 r180 top value=1.00k
R47 "CRCW060310R0FKEAHP" 0603 1490,1090 r0 top value=10.0
R48 "5106" 5106 1115,1460 r0 top value=0
R49 "CRCW0603100RFKEA" 0603 1030,560 r0 top value=100
R50 "RC0603JR-070RL" 0603 1910,1280 r180 top value=0
R51 "RC0603JR-070RL" 0603 1320,720 r270 top value=0
R52 "RC0603JR-070RL" 0603 1255.59,720 r90 top value=0
R53 "RC0603JR-070RL" 0603 1868.98,1156 r90 top value=0
R54 "RC0603JR-070RL" 0603 1740.23,1845 r180 top value=0
R55 "CRCW0603100RFKEA" 0603 1160,490 r180 top value=100
R56 "RC0603JR-070RL" 0603 2173.54,1102.43 r0 top value=0
R57 "RC0603JR-070RL" 0603 1930,1820 r0 top value=0
R58 "CRCW06031K00FKEA" 0603 900,710 r270 top value=1.00k
R59 "RC0603JR-070RL" 0603 1010,860 r270 top value=0
R60 "RC0603JR-070RL" 0603 940,860 r90 top value=0
R61 "RC1206FR-075R49L" 1206 1605,220 r0 top value=5.49
R62 "RC1206FR-075R49L" 1206 2245,220 r0 top value=5.49
R63 "CRCW06031K00FKEA" 0603 1055,1820.31 r0 top value=1.00k
R64 "RC0603FR-0737R4L" 0603 770,2140 r180 top value=37.4
R65 "RC0603FR-0710KL" 0603 910,2050 r0 top value=10.0k
R66 "CRCW06031K00FKEA" 0603 910,2120 r180 top value=1.00k
R67 "CRCW060310R0FKEAHP" 0603 1490,1150 r0 top value=10.0
R68 "CRCW0603100KFKEA" 0603 2760,2285 r180 top value=100k
R69 "ERJ-L03KF10CV" 0603 2340,2430 r0 top value=0.1
R70 "RC0603FR-0710KL" 0603 4000,2183.66 r90 top value=10.0k
R71 "RC0603JR-070RL" 0603 1470,1960 r0 top value=0
R72 "RC0603JR-070RL" 0603 2310,2070 r270 top value=0
R73 "RC0603JR-070RL" 0603 2380,2070 r270 top value=0
R74 "RC0603JR-070RL" 0603 1930,1960 r0 top value=0
R75 "RC0603JR-070RL" 0603 2450,2070 r270 top value=0
R76 "RC0603FR-075R11L" 0603 1470,2220 r0 top value=5.11
R77 "RC0603FR-075R11L" 0603 3510,224.47 r90 top value=5.11
R78 "RC0603JR-070RL" 0603 2520,2070 r270 top value=0
R79 "RC0603FR-075R11L" 0603 1927.94,2220 r0 top value=5.11
R80 "RC0603FR-0711K3L" 0603 3511.72,2055 r270 top value=11.3k
R81 "RC0603JR-070RL" 0603 4180,1160 r90 top value=0
R82 "RC0603JR-070RL" 0603 2590,2070 r270 top value=0
R83 "RC0603JR-070RL" 0603 2660,2070 r270 top value=0
R84 "RC0603JR-070RL" 0603 3480,1955 r0 top value=0
R85 "RC0805JR-070RL" 0805_HV 3100,2640 r180 top value=0
R86 "RC0603FR-0710KL" 0603 3511.72,2185 r270 top value=10.0k
R87 "RT0603BRD0749R9L" 0603 3260,992.31 r0 top value=49.9
R88 "RT0603BRD0749R9L" 0603 2810.02,1350 r180 top value=49.9
R89 "RC0603JR-070RL" 0603 2490,753.89 r90 top value=0
R90 "RC0603JR-070RL" 0603 2490,885 r90 top value=0
R91 "CRCW0603100KFKEA" 0603 2893.97,865.89 r180 top value=100k
R92 "RC0603JR-070RL" 0603 2240,925 r0 top value=0
R93 "RC0603JR-070RL" 0603 2370,924.98 r0 top value=0
R94 "RC0603JR-070RL" 0603 2480.66,1609.33 r0 top value=0
R95 "CRCW060310R0FKEAHP" 0603 3489.35,1540 r0 top value=10.0
R96 "RC0603JR-070RL" 0603 4362.44,1263.33 r0 top value=0
R97 "RC0603JR-070RL" 0603 735,920.71 r180 top value=0
R98 "RC0603JR-070RL" 0603 430,920.71 r180 top value=0
R100 "RC0603JR-070RL" 0603 2965.65,965.39 r90 top value=0
R101 "RC0603JR-070RL" 0603 2760,915 r180 top value=0
R129 "CRCW060310R0FKEAHP" 0603 3041.04,869.66 r0 top value=10.0
R130 "CRCW060310R0FKEAHP" 0603 2965,1760 r270 top value=10.0
R196 "RC0603JR-070RL" 0603 3045,1070 r0 top value=0
R197 "RC0603JR-070RL" 0603 3046.22,967.2 r270 top value=0
R198 "CRCW0603100KFKEA" 0603 3041.04,803.42 r0 top value=100k
SH-J1 "SPC02SYAN" SPC02SYAN 3850,2120.33 r270 top value=1x2
SH-J2 "SPC02SYAN" SPC02SYAN 2925,2136.5 r90 top value=1x2
SH-J3 "SPC02SYAN" SPC02SYAN 2750,756 r180 top value=1x2
SH-J4 "SPC02SYAN" SPC02SYAN 3530,717.4 r180 top value=1x2
SH-J5 "SPC02SYAN" SPC02SYAN -591.58,-440 r180 top value=1x2
SH-J6 "SPC02SYAN" SPC02SYAN 4453,360 r90 top value=1x2
SH-J7 "SPC02SYAN" SPC02SYAN 385,780 r90 top value=1x2
SH-J8 "SPC02SYAN" SPC02SYAN 545,780 r90 top value=1x2
SH-J9 "SPC02SYAN" SPC02SYAN 705,780 r90 top value=1x2
TP1 "REFP" Harwin_S2751-46R 2291.74,1220 r0 top
TP2 "REFN" Harwin_S2751-46R 2291.74,1135 r0 top
TP3 "AVSS" Harwin_S2751-46R 2207.39,771.49 r0 top
TP4 "VrefIN" Harwin_S2751-46R 2210.34,685 r0 top
TP5 "GND" Harwin_S2751-46R 4040,1710 r90 top
TP6 "EVM_5V" Harwin_S2751-46R 4160.44,1710 r90 top
TP7 "A1+" Harwin_S2751-46R 1250,2040 r0 top
TP8 "A1-" Harwin_S2751-46R 1250,1960 r0 top
TP9 "A2+" Harwin_S2751-46R 1740,2043 r180 top
TP10 "A2-" Harwin_S2751-46R 1740,1958.94 r180 top
TP11 "D+" Harwin_S2751-46R 3095,1610 r90 top
TP12 "D-" Harwin_S2751-46R 3015,1610 r90 top
TP13 "AVSS" Harwin_S2751-46R 2190,2320 r0 top
TP14 "5V_LDO" Harwin_S2751-46R 2190,2420 r0 top
TP15 "5V5" Harwin_S2751-46R 4100,2173.66 r180 top
TP16 "GND" Harwin_S2751-46R 4100,2073.66 r180 top
TP17 "GND" Keystone1573-2 150,150 r0 top
TP18 "GND" Keystone1573-2 150,2650 r0 top
TP19 "A2" Harwin_S2751-46R 385,365 r90 top
TP20 "A1" Harwin_S2751-46R 485,365 r90 top
TP21 "A0" Harwin_S2751-46R 585,365 r90 top
TP22 "GND" Harwin_S2751-46R 685,365 r90 top
U1 "REF6225IDGKR" DGK0008A_N 2367.95,770.24 r90 top
U2 "BR24G32FVT-3AGE2" TSOP65P640X120-8N 3930,610 r270 top
U3 "ADS127L21IRUKR" RUK0020B-MFG 2630,1490 r0 top
U4 "OPA192IDBVR" DBV0005A_N 1630,710 r270 top
U5 "PGA855RGT" RGT0016J-MFG 1770,1500 r0 top
U6 "OPA192IDBVR" DBV0005A_N 1080,710 r270 top
U7 "OPA192IDBVR" DBV0005A_N 900,1940 r90 top
U8 "TPS7A4700RGWR" RGW0020A 2550,2340 r0 top
U9 "TPS7A3001DRBR" DRB0008A 3400,2090 r180 top
Y1 "KC2016K32.7680C1GE00" FP-KC2016K32.7680C1GE00_SMT4_2MM0_1MM6-MFG 2914.28,1087.69 r0 top
ZZ1 "This Assembly Note is for PCB labels only" AssemblyNoteLabel 185,4319.45 r0 top
ZZ2 "These assemblies are ESD sensitive, ESD precautions shall be observed." AssemblyNote 1040,4780 r0 top
ZZ3 "These assemblies must be clean and free from flux and all contaminants. Use of no clean flux is not acceptable." AssemblyNote 185,4140.56 r0 top
ZZ4 "These assemblies must comply with workmanship standards IPC-A-610 Class 2, unless otherwise specified." AssemblyNote 185,4052 r0 top

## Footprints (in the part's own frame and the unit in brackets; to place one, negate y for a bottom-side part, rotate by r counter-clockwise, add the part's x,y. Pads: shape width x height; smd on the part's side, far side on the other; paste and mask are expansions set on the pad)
0603 [mm] "0603 from SM-752 data"
  rect 1x0.95 smd: 1(-0.8,0) 2(0.8,0)
  silkscreen extent -1.52,-0.69 1.52,0.69, body extent -0.87,-0.47 0.87,0.47, height 1
0805_HV [mil] "0805 with 30mil clearance between pads"
  rect 50x63 smd: 1(-40,0) 2(40,0)
  silkscreen extent -74,-40 74,40, body extent -43,-29 43,29, height 57
1206 [mm] "1206 from SM-752 data"
  rect 1.3x1.85 smd: 1(-1.45,0) 2(1.45,0)
  silkscreen extent -2.4,-1.21 2.4,1.21, body extent -1.7,-0.9 1.7,0.9, height 1.35
1206_190 [mm] "1206_190"
  rect 1.1x1.6 smd: 1(-1.7,0) 2(1.7,0)
  silkscreen extent -0.9,-1 0.9,1, body extent -1.75,-0.95 1.75,0.95, height 1.9
1210_270 [mm] "1210"
  rect 1.3x2.7 smd: 1(-1.45,0) 2(1.45,0)
  silkscreen extent -2.32,-1.57 2.32,1.57, body extent -1.7,-1.35 1.7,1.35, height 2.7
5106 [mm] "Keystone"
  rect 0.99x1.4 smd: 1(-0.85,0) 2(0.88,0)
  silkscreen extent -1.63,-0.97 1.65,0.97, body extent -1.06,-0.69 1.06,0.69, height 0.84
AMPHENOL_901-144-8RFX [mm] "SMA Straight Jack, TH"
  round 2 hole 1.5: 1(0,0)
  round 2.2 hole 1.7: 2(-2.54,2.54) 3(-2.54,-2.54) 4(2.54,-2.54) 5(2.54,2.54)
  silkscreen extent -3.7,-3.7 3.7,3.7, body extent -3.7,-3.7 3.7,3.7, height 9.93
APT2012_Green [mm] "SMD, 2-Leads, Body 2x1.25mm"
  rect 1.25x1.1 smd: 1(-1.175,0) 2(1.175,0)
  silkscreen extent -1.5,-1 2.4,1, body extent -1,-0.62 1,0.63, height 0.76
AssemblyNote [mil] "Assembly Note"
AssemblyNoteLabel [mil] "Assembly Note for PCB Labels"
Bumpon_SJ5003Transparent [mil] "3M Hemispherical Bumpon transparent"
  round 1 on Mech4: 0(0,0)
  silkscreen extent -228,-228 228,228, body extent -219,-219 219,219, height 197
CE_Mark_5mm [mil] "Minimum text height for CE Mark"
  silkscreen extent -138,-98 138,98
DBV0005A_N [mm] "SOT23, 5-Leads, Body 2.9x1.6mm, Pitch 0.95mm, Lead Span 2.8mm, IPC Medium Density"
  rrect17% 1x0.6 smd: 1(-1.375,0.95) 2(-1.375,0) 3(-1.375,-0.95) 4(1.375,-0.95) 5(1.375,0.95)
  silkscreen extent -0.25,-1.55 0.25,1.55, body extent -1.42,-1.46 1.42,1.46, height 1.09
DGK0008A_N [mm] "TSOP, 8-Leads, Body 3x3mm, Pitch 0.65mm, IPC Medium Density"
  oval 1.35x0.45 smd: 1(-2.225,0.975) 2(-2.225,0.325) 3(-2.225,-0.325) 4(-2.225,-0.975) 5(2.225,-0.975) 6(2.225,-0.325) 7(2.225,0.325) 8(2.225,0.975)
  silkscreen extent -2.75,-1.55 0.95,1.55, body extent -2.45,-1.5 2.45,1.5, height 0.96
DRB0008A [mm] "VSON-8"
  rrect32% 0.6x0.31 smd: 1(-1.4,0.975) 2(-1.4,0.325) 3(-1.4,-0.325) 4(-1.4,-0.975) 5(1.4,-0.975) 6(1.4,-0.325) 7(1.4,0.325) 8(1.4,0.975)
  rrect7% 1.5x1.75 smd paste-0.75: 9(0,0)
  Top Layer region: -0.7,-0.875 -0.49,-0.875 -0.471,-0.879 -0.455,-0.89 -0.444,-0.906 -0.44,-0.925 -0.44,-0.925 -0.44,-1.65 -0.436,-1.669 -0.425,-1.685 -0.409,-1.696 -0.39,-1.7 -0.39,-1.7 -0.26,-1.7 -0.241,-1.696 -0.225,-1.685 -0.214,-1.669 -0.21,-1.65 -0.21,-1.65 -0.21,-0.925 -0.206,-0.906 -0.195,-0.89 -0.179,-0.879 -0.16,-0.875 -0.16,-0.875 0.16,-0.875 0.179,-0.879 0.195,-0.89 0.206,-0.906 0.21,-0.925 0.21,-0.925 0.21,-1.65 0.21,-1.65 0.214,-1.669 0.225,-1.685 0.241,-1.696 0.26,-1.7 0.26,-1.7 0.39,-1.7 0.409,-1.696 0.425,-1.685 0.436,-1.669 0.44,-1.65 0.44,-1.65 0.44,-0.925 0.444,-0.906 0.455,-0.89 0.471,-0.879 0.49,-0.875 0.49,-0.875 0.7,-0.875 0.719,-0.871 0.735,-0.86 0.746,-0.844 0.75,-0.825 0.75,-0.825 0.75,0.825 0.746,0.844 0.735,0.86 0.719,0.871 0.7,0.875 0.7,0.875 0.49,0.875 0.471,0.879 0.455,0.89 0.444,0.906 0.44,0.925 0.44,0.925 0.44,1.65 0.436,1.669 0.425,1.685 0.409,1.696 0.39,1.7 0.39,1.7 0.26,1.7 0.241,1.696 0.225,1.685 0.214,1.669 0.21,1.65 0.21,1.65 0.21,1.65 0.21,0.925 0.206,0.906 0.195,0.89 0.179,0.879 0.16,0.875 0.16,0.875 -0.16,0.875 -0.179,0.879 -0.195,0.89 -0.206,0.906 -0.21,0.925 -0.21,0.925 -0.21,1.65 -0.214,1.669 -0.225,1.685 -0.241,1.696 -0.26,1.7 -0.26,1.7 -0.39,1.7 -0.409,1.696 -0.425,1.685 -0.436,1.669 -0.44,1.65 -0.44,1.65 -0.44,0.925 -0.444,0.906 -0.455,0.89 -0.471,0.879 -0.49,0.875 -0.49,0.875 -0.7,0.875 -0.719,0.871 -0.735,0.86 -0.746,0.844 -0.75,0.825 -0.75,0.825 -0.75,-0.825 -0.746,-0.844 -0.735,-0.86 -0.719,-0.871 -0.7,-0.875
  silkscreen extent -1.73,-1.73 1.73,1.73, body extent -1.5,-1.5 1.5,1.5, height 0.77
FCC_disclaimer [mil]
Fiducial10-30 [mm]
  round 1 smd mask+1: 1(0,0)
  Top Layer keep-out circle w1.678: c0,0 r0.75
FP-KC2016K32.7680C1GE00_SMT4_2MM0_1MM6-MFG [mm]
  rrect17% 0.6x0.8 smd paste+0 mask+0: 1(-0.9,-0.6) 2(0.9,-0.6) 3(0.9,0.6) 4(-0.9,0.6)
  silkscreen extent -1.02,-1.67 0.22,0.9, body extent -1.3,-1.1 1.3,1.1, height 0.25
Harwin_S2751-46R [mm] "Test Point, SMT"
  rect 2.2x1.4 smd: 1(0,0)
  body extent -1,-0.6 1,0.6, height 1.4
Johnson_142-0701-801 [mil] "Johnson Components recommended land pattern"
  rect 90x200 smd: 1(0,0)
  round 38 hole 18: 2(-172.5,-135) 3(172.5,-135)
  rect 95x200 smd: 2(-172.5,0) 3(172.5,0)
  rect 95x200 smd far side: 4(-172.5,0) 5(172.5,0)
  Top Layer lines w18: -172.5,0 -172.5,-135 ; 172.5,0 172.5,-135
  Bottom Layer lines w18: -172.5,0 -172.5,-135 ; 172.5,0 172.5,-135
  silkscreen extent -235,-170 235,100, body extent -190,-92 190,480, height 165
Keystone1573-2 [mm] "Double Turret"
  round 2.7 hole 2.05: 1(0,0)
  silkscreen extent -1.73,-1.73 1.73,1.73, body extent -1.18,-1.18 1.17,1.18, height 4.72
Label_650x200 [mil] "Thermal Transfer Label"
  round 1 on Mech14: 0(0,0)
  silkscreen extent -325,-100 325,100, body extent -325,-100 325,100, height 1
MOLEX_39357-0003 [mm] "Terminal Block, 3.5 mm, 3x1, TH"
  rect 1.6x1.6 hole 1.1: 1(-3.5,0)
  round 1.6 hole 1.1: 2(0,0) 3(3.5,0)
  silkscreen extent -5.61,-3.45 5.25,3.84, body extent -5.25,-3.45 5.16,3.84, height 8.51
RGT0016J-MFG [mm]
  rrect40% 0.6x0.25 smd paste+0 mask+0: 1(-1.4,0.75) 2(-1.4,0.25) 3(-1.4,-0.25) 4(-1.4,-0.75) 9(1.4,-0.75) 10(1.4,-0.25) 11(1.4,0.25) 12(1.4,0.75)
  rrect40% 0.25x0.6 smd paste+0 mask+0: 5(-0.75,-1.4) 6(-0.25,-1.4) 7(0.25,-1.4) 8(0.75,-1.4) 13(0.75,1.4) 14(0.25,1.4) 15(-0.25,1.4) 16(-0.75,1.4)
  rrect6% 1.66x1.66 smd paste-1000 mask+0: 17(0,0)
  silkscreen extent -2.37,-1.55 1.55,1.55, body extent -1.8,-1.8 1.8,1.8, height 0.25
RGW0020A [mm] "QFN, 20-Leads, Body 5x5mm, Pitch 0.65mm, Thermal Pad 3.15x3.15mm, TI Recommended"
  rrect32% 0.75x0.31 smd: 1(-2.325,1.3) 2(-2.325,0.65) 3(-2.325,0) 4(-2.325,-0.65) 5(-2.325,-1.3) 11(2.325,-1.3) 12(2.325,-0.65) 13(2.325,0) 14(2.325,0.65) 15(2.325,1.3)
  rrect32% 0.31x0.75 smd: 6(-1.3,-2.325) 7(-0.65,-2.325) 8(0,-2.325) 9(0.65,-2.325) 10(1.3,-2.325) 16(1.3,2.325) 17(0.65,2.325) 18(0,2.325) 19(-0.65,2.325) 20(-1.3,2.325)
  rrect7% 1.37x1.37 on Top Paste: 21(-0.785,-0.785) 21(-0.785,0.785) 21(0.785,-0.785) 21(0.785,0.785)
  rrect3% 3.15x3.15 smd paste-1.575: 21(0,0)
  silkscreen extent -2.73,-2.73 2.73,2.73, body extent -2.55,-2.55 2.55,2.55, height 1.01
RUK0020B-MFG [mm]
  rrect50% 0.6x0.2 smd paste+0 mask+0: 1(-1.4,0.8) 2(-1.4,0.4) 3(-1.4,0) 4(-1.4,-0.4) 5(-1.4,-0.8) 11(1.4,-0.8) 12(1.4,-0.4) 13(1.4,0) 14(1.4,0.4) 15(1.4,0.8)
  rrect50% 0.2x0.6 smd paste+0 mask+0: 6(-0.8,-1.4) 7(-0.4,-1.4) 8(0,-1.4) 9(0.4,-1.4) 10(0.8,-1.4) 16(0.8,1.4) 17(0.4,1.4) 18(0,1.4) 19(-0.4,1.4) 20(-0.8,1.4)
  rrect6% 1.7x1.7 smd paste-1000 mask+0: 21(0,0)
  silkscreen extent -2.4,-1.55 1.55,1.55, body extent -1.8,-1.8 1.8,1.8, height 0.25
Samtec_QTH-030-01-x-D-A [mil] "Header (Shrouded), 19.7mil, 30x2, SMT"
  rect 12x57 smd: 1(-285.7,121.5) 2(-285.7,-121.5) 3(-266,121.5) 4(-266,-121.5) 5(-246.3,121.5) 6(-246.3,-121.5) 7(-226.6,121.5) 8(-226.6,-121.5) 9(-206.9,121.5) 10(-206.9,-121.5) 11(-187.2,121.5) 12(-187.2,-121.5) 13(-167.5,121.5) 14(-167.5,-121.5) 15(-147.8,121.5) 16(-147.8,-121.5) 17(-128.1,121.5) 18(-128.1,-121.5) 19(-108.4,121.5) 20(-108.4,-121.5) 21(-88.7,121.5) 22(-88.7,-121.5) 23(-69,121.5) 24(-69,-121.5) 25(-49.3,121.5) 26(-49.3,-121.5) 27(-29.6,121.5) 28(-29.6,-121.5) 29(-9.9,121.5) 30(-9.9,-121.5) 31(9.8,121.5) 32(9.8,-121.5) 33(29.5,121.5) 34(29.5,-121.5) 35(49.2,121.5) 36(49.2,-121.5) 37(68.9,121.5) 38(68.9,-121.5) 39(88.6,121.5) 40(88.6,-121.5) 41(108.3,121.5) 42(108.3,-121.5) 43(128,121.5) 44(128,-121.5) 45(147.7,121.5) 46(147.7,-121.5) 47(167.4,121.5) 48(167.4,-121.5) 49(187.1,121.5) 50(187.1,-121.5) 51(206.8,121.5) 52(206.8,-121.5) 53(226.5,121.5) 54(226.5,-121.5) 55(246.2,121.5) 56(246.2,-121.5) 57(265.9,121.5) 58(265.9,-121.5) 59(285.6,121.5) 60(285.6,-121.5)
  round 0 hole 40 unplated: MH1(-364,80) MH2(364,80)
  rect 100x25 smd: MP1(-332.7,0) MP4(332.3,0)
  rect 185x25 smd: MP2(-125.2,0) MP3(124.8,0)
  silkscreen extent -394,-118 394,131, body extent -394,-140 394,140, height 170
Samtec_TSW-109-07-G-D [mm] "Samtec 100mil, 2x9, 230 mil above insulator"
  rrect6% 1.65x1.65 hole 1.016: 1(-10.16,-1.27)
  round 1.65 hole 1.016: 2(-10.16,1.27) 3(-7.62,-1.27) 4(-7.62,1.27) 5(-5.08,-1.27) 6(-5.08,1.27) 7(-2.54,-1.27) 8(-2.54,1.27) 9(0,-1.27) 10(0,1.27) 11(2.54,-1.27) 12(2.54,1.27) 13(5.08,-1.27) 14(5.08,1.27) 15(7.62,-1.27) 16(7.62,1.27) 17(10.16,-1.27) 18(10.16,1.27)
  silkscreen extent -12.45,-2.54 11.43,2.54, body extent -11.43,-2.54 11.43,2.54, height 8.38
SOD-123 [mm] "On Semi recommended land pattern"
  rect 0.915x1.22 smd: 1(-1.637,0) 2(1.637,0)
  silkscreen extent -2.74,-1.17 2.03,1.17, body extent -1.93,-0.9 1.93,0.9, height 1.35
SOD-323 [mm] "NXP recommended land pattern"
  rect 0.6x0.6 smd paste-0.05: 1(-1.1,0) 2(1.1,0)
  silkscreen extent -2.06,-0.86 1.53,0.86, body extent -1.3,-0.67 1.3,0.68, height 1.1
SPC02SYAN [mil] "SULLINS"
  round 1 on Mech3: 0(0,0)
  body extent -98,-47 99,47, height 366
TERM_BLK_ED555-2DS [mil]
  rrect4% 100x100 hole 50: 1(0,0)
  round 100 hole 50: 2(138,0)
  silkscreen extent -93,-161 215,113, body extent -69,-150 207,106, height 323
TI_Stacked_Overlay_Small [mil]
  silkscreen extent -418,-98 418,98
TSOP65P640X120-8N [mm] "TSOP, 8-Leads, Body 3.1x4.5mm (max), Pitch 0.65mm, IPC Medium Density"
  oval 1.55x0.35 smd mask+0.08: 1(-2.875,0.975) 2(-2.875,0.325) 3(-2.875,-0.325) 4(-2.875,-0.975) 5(2.875,-0.975) 6(2.875,-0.325) 7(2.875,0.325) 8(2.875,0.975)
  silkscreen extent -1.7,-1.55 1.7,1.55, body extent -2.25,-1.55 2.25,1.55, height 1.21
TSW-102-07-G-S [mm] "Samtec 100mil, 1x2, 230 mil above insulator"
  rrect50% 1.65x1.65 hole 1.016: 1(-1.27,0)
  round 1.65 hole 1.016: 2(1.27,0)
  silkscreen extent -3.17,-1.27 2.54,1.27, body extent -2.54,-1.27 2.54,1.27, height 8.38
TSW-103-07-G-S [mm] "Samtec 100mil, 1x3, 230 mil above insulator"
  rrect50% 1.65x1.65 hole 1.016: 1(-2.54,0)
  round 1.65 hole 1.016: 2(0,0) 3(2.54,0)
  body extent -3.81,-1.27 3.81,1.27, height 8.38
TSW-104-07-G-S [mm] "Samtec 100mil, 1x4, 230 mil above insulator"
  rrect50% 1.65x1.65 hole 1.016: 1(-3.81,0)
  round 1.65 hole 1.016: 2(-1.27,0) 3(1.27,0) 4(3.81,0)
  body extent -5.08,-1.27 5.08,1.27, height 8.38
WEEE_Minimum [mil] "WEEElie bin"
  silkscreen extent -95,-172 99,104
Wurth_WA-SMSI [mm] "ROUND STANDOFF M3 STEEL 5MM"
  round 0 hole 4.4 unplated: ""(0,0)
  Top Layer region: -3.711,0 -3.666,0.581 -3.53,1.147 -3.307,1.685 -3.003,2.182 -2.624,2.624 -2.182,3.003 -1.685,3.307 -1.147,3.53 -0.581,3.666 0,3.711 0.581,3.666 1.147,3.53 1.685,3.307 2.182,3.003 2.624,2.624 3.003,2.182 3.307,1.685 3.53,1.147 3.666,0.581 3.711,0 3.7,0 2.466,0 2.418,0.481 2.278,0.944 2.05,1.37 1.744,1.744 1.37,2.05 0.944,2.278 0.481,2.418 0,2.466 -0.481,2.418 -0.944,2.278 -1.37,2.05 -1.744,1.744 -2.05,1.37 -2.278,0.944 -2.418,0.481 -2.466,0 -2.454,0
  Top Layer region: -3.711,0 -3.666,-0.581 -3.53,-1.147 -3.307,-1.685 -3.003,-2.182 -2.624,-2.624 -2.182,-3.003 -1.685,-3.307 -1.147,-3.53 -0.581,-3.666 0,-3.711 0.581,-3.666 1.147,-3.53 1.685,-3.307 2.182,-3.003 2.624,-2.624 3.003,-2.182 3.307,-1.685 3.53,-1.147 3.666,-0.581 3.711,0 3.7,0 2.466,0 2.418,-0.481 2.278,-0.944 2.05,-1.37 1.744,-1.744 1.37,-2.05 0.944,-2.278 0.481,-2.418 0,-2.466 -0.481,-2.418 -0.944,-2.278 -1.37,-2.05 -1.744,-1.744 -2.05,-1.37 -2.278,-0.944 -2.418,-0.481 -2.466,0 -2.454,0
  silkscreen extent -4.1,-4.1 4.1,4.1, body extent -2.99,-2.98 2.99,3, height 5

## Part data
C1 C4 C7 C9 C13 C16 C18 C19 C21 C23 C24 C27 C35 C37 C39 C41 C46 C55: library part CMP-0006856-6, "CAP, CERM, 0.1 uF, 25 V, +/- 5%, X7R, 0603", Cap_Case=0603, Manufacturer=Kemet, Supplier Part Number 1=399-1282-1-ND, TempCo=X7R, Tolerance_%=5%, Value1=Unknown, Value2=25V, ValueDisplayed=0.1uF
C2 C20 C26 C45: library part CMP-0081849-1, "CAP, CERM, 10 µF,  V,+/- 10%, X7R, 0805", Cap_Case=0805, Manufacturer=MuRata, Supplier Part Number 1=490-10516-2-ND, TempCo=X7R, Tolerance_%=10%, ValueDisplayed=10µF
C3 C49: library part CMP-0080066-1, "CAP, CERM, 22 µF, 25 V,+/- 10%, X7R, 1210", Cap_Case=1210, Manufacturer="Samsung Electro-Mechanics", Supplier Part Number 1=1276-3391-1-ND, TempCo=X7R, Tolerance_%=10%, Value2=25V, ValueDisplayed=22µF
C5 C44: library part CMP-0079607-1, "CAP, CERM, 1 µF, 16 V,+/- 10%, X7R, AEC-Q200 Grade 1, 0603", Cap_Case=0603, Manufacturer=TDK, Supplier Part Number 1=445-12539-1-ND, TempCo=X7R, Tolerance_%=10%, Value2=16V, ValueDisplayed=1µF
C6 C8 C10 C11 C12 C15 C42 C43 C50 C51 C53 C54: library part CMP-0006867-4, "CAP, CERM, 1 uF, 25 V, +/- 10%, X7R, 0603", Cap_Case=0603, Manufacturer=Kemet, Supplier Part Number 1=399-7376-1-ND, TempCo=X7R, Tolerance_%=10%, Value1=Unknown, Value2=25V, ValueDisplayed=1uF
C14 C17 C48 C52 C56: library part CMP-0008589-2, "CAP, CERM, 10 uF, 25 V, +/- 10%, X7R, 1206_190", Cap_Case=1206, Manufacturer=Kemet, Supplier Part Number 1=399-7442-1-ND, TempCo=X7R, Tolerance_%=10%, Value1=Unknown, Value2=25V, ValueDisplayed=10uF
C25 C40: library part CMP-0007159-4, "CAP, CERM, 1000 pF, 25 V, +/- 5%, C0G/NP0, 0603", Cap_Case=0603, Manufacturer=MuRata, Supplier Part Number 1=GRM1885C1E102JA01D-ND, TempCo=C0G/NP0, Tolerance_%=5%, Value1=Unknown, Value2=25V, ValueDisplayed=1000pF
C28 C67: library part CMP-0006837-4, "CAP, CERM, 0.1 uF, 50 V, +/- 10%, X7R, 0603", Cap_Case=0603, Manufacturer="Wurth Elektronik", TempCo=X7R, Tolerance_%=10%, Value1=Unknown, Value2=50V, ValueDisplayed=0.1uF
C30: library part CMP-0006842-4, "CAP, CERM, 1000 pF, 50 V, +/- 5%, C0G/NP0, 0603", Cap_Case=0603, Manufacturer=Kemet, Supplier Part Number 1=317202, TempCo=C0G/NP0, Tolerance_%=5%, Value1=Unknown, Value2=50V, ValueDisplayed=1000pF
C32 C66: library part CMP-0080088-1, "CAP, CERM, 25pF, 100 V,+/- 2%, C0G/NP0, 0603", Cap_Case=0603, Manufacturer=AVX, Supplier Part Number 1=478-10197-1-ND, TempCo=C0G/NP0, Tolerance_%=2%, Value2=100V, ValueDisplayed=25pF
C33 C63: library part CMP-0006762-4, "CAP, CERM, 100 pF, 50 V, +/- 1%, C0G/NP0, 0603", Cap_Case=0603, Manufacturer=AVX, Supplier Part Number 1=478-6202-1-ND, TempCo=C0G/NP0, Tolerance_%=1%, Value1=Unknown, Value2=50V
C34 C64: library part CMP-0008167-3, "CAP, CERM, 10 pF, 100 V, +/- 5%, C0G/NP0, 0805", Cap_Case=0805, Manufacturer=MuRata, Supplier Part Number 1=490-1590-1-ND, TempCo=C0G/NP0, Tolerance_%=5%, Value1=Unknown, Value2=100V, ValueDisplayed=10pF
C36 C65: library part CMP-0080093-1, "CAP, CERM, 51 pF, 50 V,+/- 1%, C0G/NP0, 0603", Cap_Case=0603, Manufacturer=Kemet, Supplier Part Number 1=399-14525-1-ND, TempCo=C0G/NP0, Tolerance_%=1%, Value2=50V, ValueDisplayed=51pF
C38 C57: library part CMP-0079995-1, "CAP, CERM, 0.01 µF, 25 V,+/- 1%, C0G/NP0, 0603", Cap_Case=0603, Manufacturer=Kemet, Supplier Part Number 1=399-8985-1-ND, TempCo=C0G/NP0, Tolerance_%=1%, Value2=25V, ValueDisplayed=0.01µF
C47: library part CMP-0080742-1, "CAP, CERM, 0.033 µF, 50 V,+/- 5%, C0G/NP0, AEC-Q200 Grade 1, 0805", Cap_Case=0805, Manufacturer=TDK, Supplier Part Number 1=445-6950-1-ND, TempCo=C0G/NP0, Tolerance_%=5%, Value2=50V, ValueDisplayed=0.033µF
C58 C59 C127: library part CMP-0007170-4, "CAP, CERM, 10 pF, 50 V, +/- 5%, C0G/NP0, 0603", Cap_Case=0603, Manufacturer=MuRata, Supplier Part Number 1=490-1403-1-ND, TempCo=C0G/NP0, Tolerance_%=5%, Value1=Unknown, Value2=50V, ValueDisplayed=10pF
C60: library part CMP-0007580-2, "CAP, CERM, 100 pF, 50 V, +/- 5%, C0G/NP0, 0805", Cap_Case=0805, Manufacturer=AVX, Supplier Part Number 1=478-1316-1-ND, TempCo=C0G/NP0, Tolerance_%=5%, Value1="0.356 ohm", Value2=50V, ValueDisplayed=10nF
C61: library part CMP-0007517-2, "CAP, CERM, 100 pF, 100 V, +/- 5%, C0G/NP0, 0805", Cap_Case=0805, Manufacturer=AVX, Supplier Part Number 1=478-1284-1-ND, TempCo=C0G/NP0, Tolerance_%=5%, Value1="0.356 ohm", Value2=100V, ValueDisplayed=100pF
C62: library part CMP-0006953-4, "CAP, CERM, 560 pF, 50 V, +/- 5%, C0G/NP0, 0603", Cap_Case=0603, Manufacturer=Kemet, Supplier Part Number 1=399-3287-1-ND, TempCo=C0G/NP0, Tolerance_%=5%, Value1=Unknown, Value2=50V, ValueDisplayed=560pF
D1 D2 D8: library part CMP-0005824-4, "Diode, TVS, Uni, 36 V, 75 Vc, SOD-323", Manufacturer=Bourns, Value1=500W
D3: library part CMP-0002953-3, "LED, Green, SMD", Color=Green, Manufacturer=Kingbright, Power_TotalModule=75mW, Value1=0.075W, Value2=2.65V
D4 D5 D6: library part CMP-0005787-3, "Diode, Zener, 5.6 V, 500 mW, SOD-123", Manufacturer="ON Semiconductor", Power_W=500mW, Value1=0.5W
D7: library part CMP-0005780-3, "Diode, Zener, 3 V, 500 mW, SOD-123", Manufacturer="ON Semiconductor", Power_W=500mW, Value1=0.5W
FID1 FID2 FID3: library part CMP-0077181-1, "Fiducial mark.  There is nothing to buy or mount.", Manufacturer=N/A
H4 H5 H6 H7: library part CMP-0003620-1, "Bumpon, Hemisphere, 0.44 X 0.20, Clear", Manufacturer=3M, Supplier Part Number 1=SJ5303-7-ND
H8 H9: library part CMP-0003785-1, "ROUND STANDOFF M3 STEEL 5MM", Manufacturer="Wurth Elektronik", Supplier Part Number 1=732-5272-1-ND
J1: library part CMP-0075558-1, "Header(Shrouded), 19.7mil, 30x2, Gold, SMT", Manufacturer=Samtec, Supplier Part Number 1=SAM8185-ND
J2: library part CMP-0075464-1, "Header, 100mil, 9x2, Gold, TH", Color=Black, Current_A=6.3A, Manufacturer=Samtec, Supplier Part Number 1=SAM1028-09-ND, Voltage_V=550V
